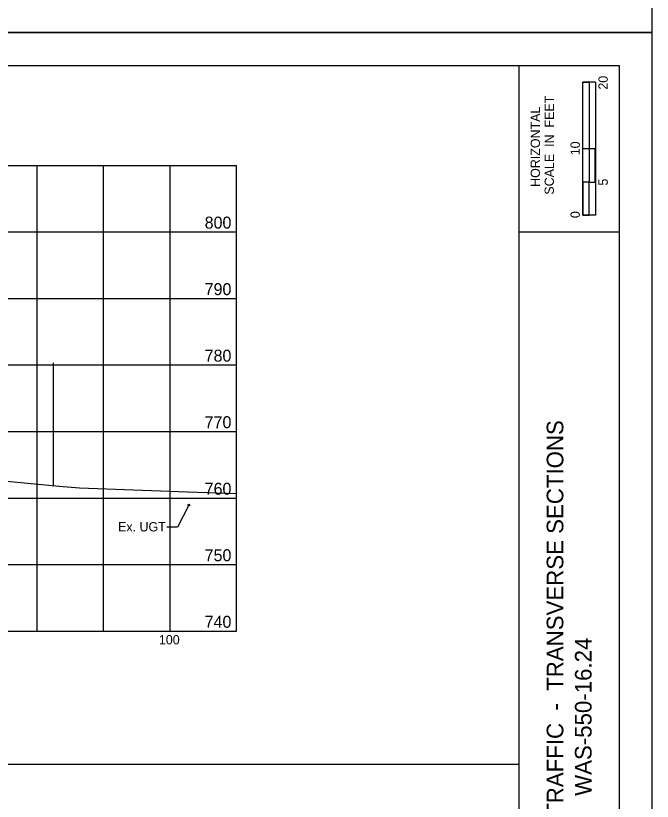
# Model space of a CAD drawing. Extents: x -1395 to 1843, y -1176 to 1887.
# Drawn here: x 488.6 to 680, y -671.2 to -435 of the extents above; entities that cross this region are included whole.
import ezdxf

# ---------------------------------------------------------------- set-up
doc = ezdxf.new("R2010")
doc.units = 0
for name, color, linetype in [('GE_X_Alignment', 7, 'Continuous'), ('HY_X_Water_Edge', 7, 'Continuous'), ('RD_X_GR_Lt', 7, 'Continuous'), ('RW_P_Esmt_TMP', 7, 'Continuous'), ('SH_Border', 7, 'Continuous'), ('SH_Cut_Line', 7, 'Continuous'), ('SH_Data', 7, 'Continuous'), ('SH_Named_Boundary', 7, 'Continuous'), ('SV_X_Break_Lines', 7, 'Continuous'), ('XS_P_Pavt_Surface', 7, 'Continuous')]:
    doc.layers.add(name, color=color, linetype=linetype)

msp = doc.modelspace()

# ---------------------------------------------------------------- linework, layer by layer
at = {"layer": 'GE_X_Alignment'}
for p, q in [((115, -480), (555, -480)), ((540.66, -582.1), (537.25, -588.77)), ((537.25, -588.77), (534.06, -588.77))]:
    msp.add_line(p, q, dxfattribs=at)
at = {"layer": 'HY_X_Water_Edge'}
msp.add_lwpolyline([(473.24, -573.73), (501.62, -576.48), (507.82, -576.93), (540.21, -578.09), (555, -578.63)], dxfattribs=at)
at = {"layer": 'RD_X_GR_Lt'}
msp.add_circle((540.66, -582.1), 0.25, dxfattribs=at)
at = {"layer": 'RW_P_Esmt_TMP'}
for p, q in [((495, -620), (495, -480)), ((515, -620), (515, -480)), ((535, -620), (535, -480)), ((555, -620), (555, -480)), ((476.61, -500), (555, -500)), ((336.74, -520), (555, -520)), ((115, -540), (555, -540)), ((115, -560), (555, -560)), ((459.44, -580), (555, -580)), ((115, -600), (555, -600)), ((115, -620), (555, -620))]:
    msp.add_line(p, q, dxfattribs=at)
at = {"layer": 'SH_Border'}
for points in [[(0, -440), (680, -440), (680, 0), (0, 0)], [(0, -880), (680, -880), (680, -440), (0, -440)]]:
    msp.add_lwpolyline(points, close=True, dxfattribs=at)
at = {"layer": 'SH_Cut_Line'}
for p, q in [((640, -870), (640, -450)), ((640, -500), (670, -500))]:
    msp.add_line(p, q, dxfattribs=at)
msp.add_lwpolyline([(30, -450), (670, -450), (670, -870), (30, -870)], close=True, dxfattribs=at)
at = {"layer": 'SH_Named_Boundary'}
for p, q in [((659.13, -495), (659.13, -455)), ((662.88, -455), (659.13, -455)), ((659.13, -475), (659.13, -455)), ((659.13, -455), (661, -455)), ((661, -455), (661.02, -455)), ((661.02, -455), (661.02, -475)), ((662.88, -455), (662.88, -495)), ((661.02, -475), (659.13, -475)), ((662.87, -475), (661, -475)), ((661, -475), (661, -485)), ((662.87, -485), (662.87, -475)), ((661, -485), (659.13, -485)), ((659.13, -485), (659.13, -495)), ((661, -495), (661, -485)), ((661, -485), (662.87, -485)), ((662.88, -495), (659.13, -495)), ((659.13, -495), (661, -495))]:
    msp.add_line(p, q, dxfattribs=at)
at = {"layer": 'SV_X_Break_Lines'}
msp.add_line((500, -576.32), (500, -539.4), dxfattribs=at)
at = {"layer": 'XS_P_Pavt_Surface'}
msp.add_line((30, -660), (640, -660), dxfattribs=at)

# ---------------------------------------------------------------- texts
at = {"layer": 'SH_Data'}
for s, height, p in [('800', 3.6, (545.41, -499)), ('790', 3.6, (545.41, -519)), ('780', 3.6, (545.41, -539)), ('770', 3.6, (545.41, -559)), ('760', 3.6, (545.41, -579)), ('Ex. UGT', 2.8, (519.36, -590.04)), ('750', 3.6, (545.41, -599)), ('740', 3.6, (545.41, -619)), ('100', 2.8, (531.65, -624))]:
    msp.add_text(s, height=height, dxfattribs=at).set_placement(p)
at = {"layer": 'SH_Named_Boundary'}
for s, height, p in [('20', 2.8, (666.62, -457.23)), ('SCALE  IN  FEET', 2.8, (650.42, -488.8)), ('HORIZONTAL', 2.8, (646.22, -486.46)), ('10', 2.8, (658.21, -476.96)), ('5', 2.8, (666.62, -486.07)), ('0', 2.8, (658.21, -495.85)), ('MAINTENANCE  OF  TRAFFIC  -  TRANSVERSE SECTIONS', 5, (653.25, -741.22)), ('WAS-550-16.24', 5, (661.75, -669.54))]:
    msp.add_text(s, height=height, rotation=90, dxfattribs=at).set_placement(p)

doc.saveas('drawing.dxf')
